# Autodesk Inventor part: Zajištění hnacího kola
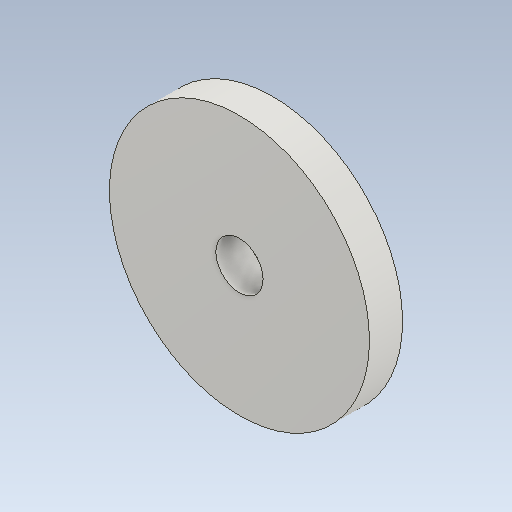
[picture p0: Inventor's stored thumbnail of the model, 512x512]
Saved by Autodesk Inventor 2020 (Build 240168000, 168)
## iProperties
Created: 2025-03
Part Number: Zajištění hnacího kola
Material: Ocel
Document SubType Name: Modeling
Designer: doma
Density: 7.85 g/cm^3
Appearance: Ocel
Mass: 126.236 g
Surface Area: 60.24 cm^2
Volume: 16.081 cm^3
Author: doma
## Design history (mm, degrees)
sketch "Náčrt1"
  geometry: C1 r 27.5 at (0, 0); C2 r 5 at (0, 0); 1 further point
  constraints: 2 centre point, 2 coincident
  dimensions: "d0" = 55 diameter of C1; "d1" = 10 diameter of C2
extrude "Vysunutí1" new body sketch "Náčrt1" distance "d2" = 7; taper "d3" = 0 deg
node "Těleso1"
